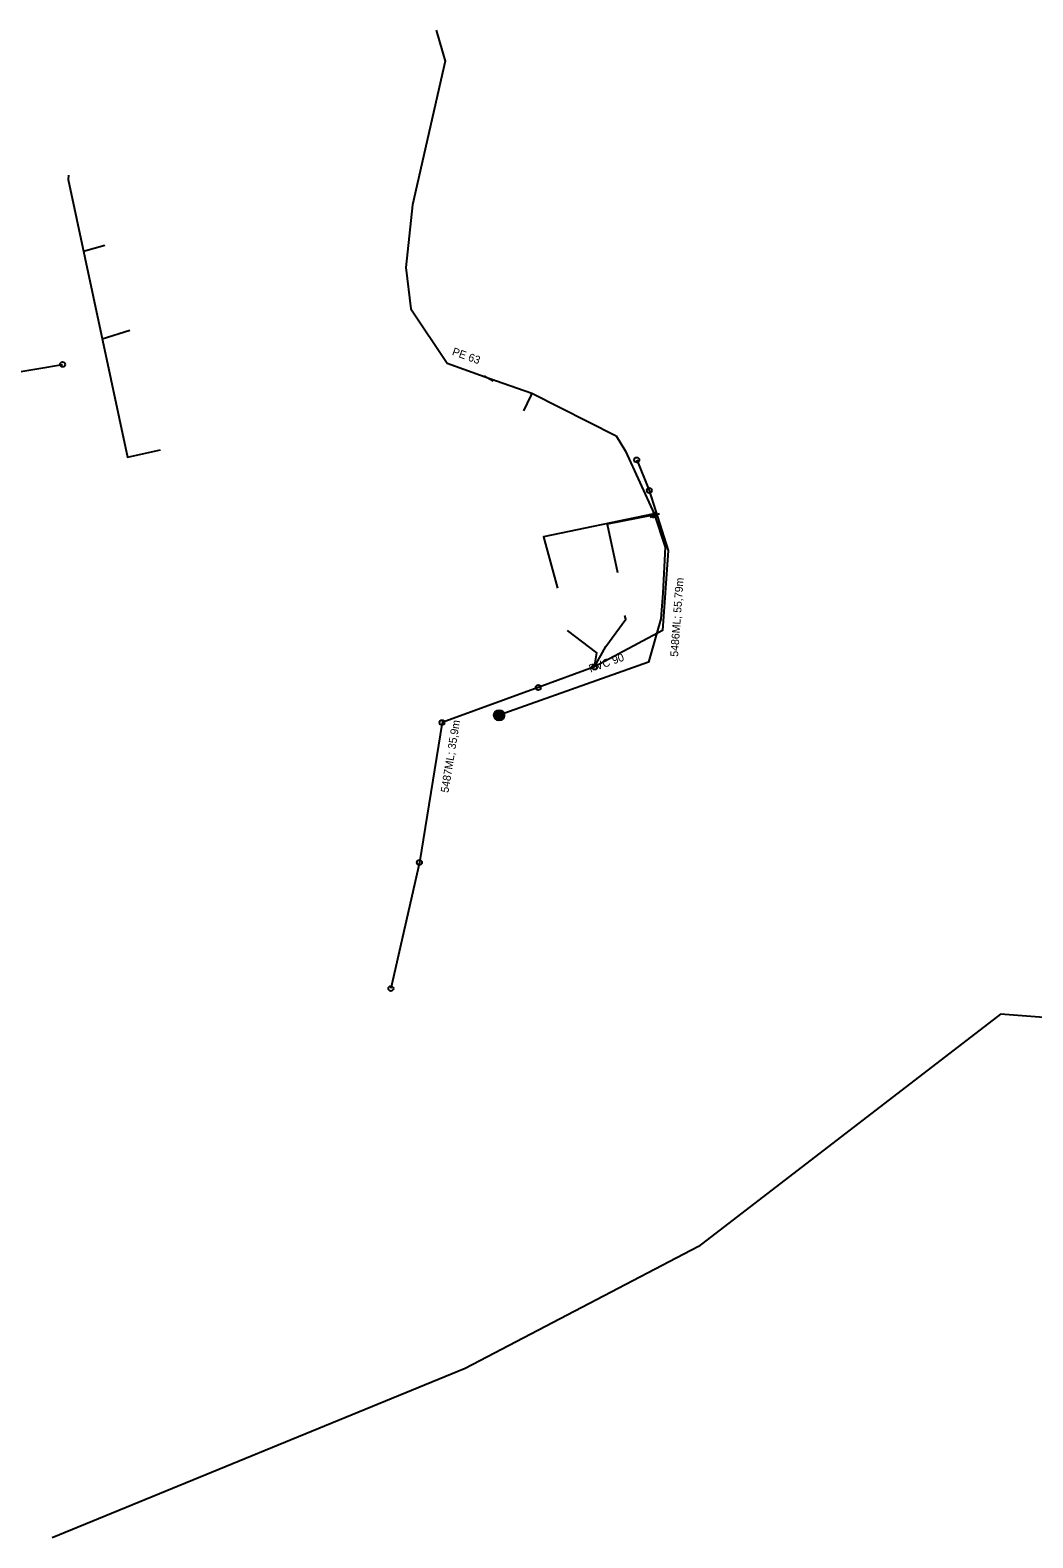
# Model space of a CAD drawing. Extents: x -867696 to -865033, y -1042522 to -1039817.
# Drawn here: x -865818.6 to -865564.5, y -1040306.4 to -1039924.3 of the extents above; entities that cross this region are included whole.
import ezdxf

# ---------------------------------------------------------------- set-up
doc = ezdxf.new("R2010")
doc.units = 0
for name, color, linetype in [('KN - destova', 7, 'Continuous'), ('KN - jednotna', 7, 'Continuous'), ('KN - popis usek delka', 7, 'Continuous'), ('KN - pripojka', 7, 'Continuous'), ('KN - sachta komora', 7, 'Continuous'), ('Level 1', 7, 'Continuous'), ('V - hydrant', 7, 'Continuous'), ('V - ostatni', 7, 'Continuous'), ('V - popis material', 7, 'Continuous'), ('V - pripojka', 7, 'Continuous'), ('V - rozvadeci', 7, 'Continuous')]:
    doc.layers.add(name, color=color, linetype=linetype)

# ---------------------------------------------------------------- blocks, each defined once
blk = doc.blocks.new('100.M')
at = {"layer": 'Level 1'}
blk.add_circle((0, 0), 1.27, dxfattribs=at)
blk = doc.blocks.new('111')
at = {"layer": 'Level 1'}
for p, q in [((0.42, 0.72), (-0.83, 0)), ((-0.83, 0), (0.42, -0.72)), ((0.42, -0.72), (0.42, 0.72))]:
    blk.add_line(p, q, dxfattribs=at)
blk = doc.blocks.new('160')
at = {"layer": 'Level 1'}
for p, q in [((-1.26, -0.04), (0.05, 1.27)), ((-1.26, -0.06), (0.06, 1.27)), ((-1.26, -0.07), (0.08, 1.27)), ((-1.26, -0.09), (0.09, 1.27)), ((-1.26, 0.11), (-0.12, 1.26)), ((-1.26, 0.1), (-0.1, 1.26)), ((-1.26, 0.08), (-0.09, 1.26)), ((-1.26, 0.07), (-0.07, 1.26)), ((-1.26, 0.06), (-0.06, 1.26)), ((-1.26, 0.04), (-0.04, 1.26)), ((-1.26, 0.03), (-0.03, 1.26)), ((-1.26, 0.01), (-0.01, 1.26)), ((-1.26, 0), (0, 1.26)), ((-1.26, -0.02), (0.02, 1.26)), ((-1.26, -0.03), (0.03, 1.26)), ((-1.26, -0.1), (0.1, 1.26)), ((-1.26, -0.11), (0.12, 1.26)), ((-1.26, -0.13), (0.13, 1.26)), ((-1.26, -0.14), (0.14, 1.26)), ((-1.26, 0.17), (-0.18, 1.25)), ((-1.26, 0.15), (-0.16, 1.25)), ((-1.26, 0.14), (-0.15, 1.25)), ((-1.26, 0.13), (-0.13, 1.25)), ((-1.26, -0.16), (0.15, 1.25)), ((-1.26, -0.17), (0.16, 1.25)), ((-1.25, 0.21), (-0.21, 1.25)), ((-1.25, 0.19), (-0.19, 1.25)), ((-1.25, -0.18), (0.17, 1.25)), ((-1.25, -0.19), (0.19, 1.25)), ((-1.25, -0.2), (0.2, 1.24)), ((-1.25, -0.21), (0.21, 1.24)), ((-1.24, 0.25), (-0.24, 1.25)), ((-1.24, 0.23), (-0.22, 1.25)), ((-1.24, -0.22), (0.22, 1.24)), ((-1.24, -0.24), (0.23, 1.24)), ((-1.24, -0.25), (0.25, 1.24)), ((-1.23, 0.27), (-0.26, 1.24)), ((-1.23, 0.29), (-0.28, 1.23)), ((-1.23, -0.26), (0.26, 1.23)), ((-1.23, -0.27), (0.27, 1.23)), ((-1.23, -0.28), (0.28, 1.23)), ((-1.23, -0.29), (0.29, 1.23)), ((-1.22, 0.3), (-0.3, 1.23)), ((-1.22, 0.32), (-0.32, 1.22)), ((-1.22, -0.3), (0.31, 1.22)), ((-1.22, -0.32), (0.32, 1.22)), ((-1.22, -0.33), (0.33, 1.22)), ((-1.21, -0.34), (0.34, 1.22)), ((-1.21, -0.35), (0.35, 1.22)), ((-1.21, 0.36), (-0.36, 1.21)), ((-1.21, 0.34), (-0.34, 1.21)), ((-1.21, -0.36), (0.36, 1.21)), ((-1.21, -0.37), (0.38, 1.21)), ((-1.2, -0.38), (0.39, 1.21)), ((-1.2, 0.38), (-0.38, 1.2)), ((-1.2, -0.39), (0.4, 1.2)), ((-1.2, -0.41), (0.41, 1.2)), ((-1.2, 0.4), (-0.4, 1.19)), ((-1.19, -0.42), (0.42, 1.2)), ((-1.19, 0.42), (-0.43, 1.19)), ((-1.19, -0.43), (0.43, 1.19)), ((-1.19, -0.44), (0.44, 1.19)), ((-1.19, 0.44), (-0.45, 1.18)), ((-1.19, -0.45), (0.45, 1.18)), ((-1.18, -0.46), (0.46, 1.18)), ((-1.18, 0.46), (-0.47, 1.17)), ((-1.18, -0.47), (0.47, 1.17)), ((-1.17, 0.48), (-0.49, 1.17)), ((-1.17, -0.48), (0.48, 1.17)), ((-1.17, -0.49), (0.49, 1.16)), ((-1.16, 0.51), (-0.51, 1.16)), ((-1.16, -0.5), (0.5, 1.16)), ((-1.16, -0.51), (0.5, 1.16)), ((-1.15, -0.52), (0.51, 1.15)), ((-1.15, -0.53), (0.52, 1.15)), ((-1.14, 0.54), (-0.53, 1.15)), ((-1.14, -0.54), (0.53, 1.14)), ((-1.14, -0.54), (0.54, 1.14)), ((-1.13, -0.55), (0.55, 1.13)), ((-1.13, -0.56), (0.56, 1.13)), ((-1.12, 0.58), (-0.56, 1.14)), ((-1.12, -0.57), (0.57, 1.12)), ((-1.12, -0.58), (0.58, 1.12)), ((-1.11, -0.59), (0.59, 1.11)), ((-1.11, -0.6), (0.6, 1.11)), ((-1.1, 0.61), (-0.6, 1.11)), ((-1.1, -0.61), (0.61, 1.11)), ((-1.1, -0.62), (0.62, 1.1)), ((-1.09, -0.63), (0.63, 1.1)), ((-1.09, 0.64), (-0.64, 1.09)), ((-1.09, -0.64), (0.64, 1.09)), ((-1.08, -0.65), (0.65, 1.09)), ((-1.08, -0.65), (0.66, 1.08)), ((-1.07, -0.66), (0.67, 1.08)), ((-1.07, -0.67), (0.68, 1.07)), ((-1.07, 0.67), (-0.68, 1.06)), ((-1.06, -0.68), (0.69, 1.07)), ((-1.06, -0.69), (0.69, 1.06)), ((-1.05, -0.7), (0.7, 1.05)), ((-1.05, -0.71), (0.71, 1.05)), ((-1.05, 0.7), (-0.71, 1.04)), ((-1.04, -0.72), (0.72, 1.04)), ((-1.04, -0.73), (0.72, 1.04)), ((-1.03, -0.74), (0.73, 1.03)), ((-1.03, -0.75), (0.74, 1.02)), ((-1.03, 0.73), (-0.75, 1.01)), ((-1.02, -0.75), (0.75, 1.02)), ((-1.01, -0.76), (0.76, 1.01)), ((-1.01, -0.77), (0.76, 1)), ((-1, -0.77), (0.77, 1)), ((-0.99, -0.78), (0.78, 0.99)), ((-0.99, -0.79), (0.79, 0.98)), ((-0.98, -0.8), (0.79, 0.98)), ((-0.97, -0.8), (0.8, 0.97)), ((-0.97, -0.81), (0.81, 0.97)), ((-0.96, -0.82), (0.82, 0.96)), ((-0.95, -0.83), (0.83, 0.95)), ((-0.95, -0.83), (0.83, 0.95)), ((-0.94, -0.84), (0.84, 0.94)), ((-0.93, -0.85), (0.85, 0.93)), ((-0.93, -0.86), (0.86, 0.93)), ((-0.92, -0.86), (0.86, 0.92)), ((-0.91, 0.87), (-0.79, 0.99)), ((-0.91, -0.87), (0.87, 0.91)), ((-0.91, -0.88), (0.88, 0.91)), ((-0.9, -0.88), (0.89, 0.9)), ((-0.89, -0.89), (0.89, 0.89)), ((-0.88, -0.9), (0.9, 0.89)), ((-0.88, -0.91), (0.91, 0.88)), ((-0.87, -0.91), (0.92, 0.88)), ((-0.86, -0.92), (0.93, 0.87)), ((-0.86, -0.93), (0.93, 0.86)), ((-0.85, -0.94), (0.94, 0.85)), ((-0.84, -0.94), (0.94, 0.84)), ((-0.84, -0.95), (0.95, 0.84)), ((-0.83, -0.96), (0.96, 0.83)), ((-0.82, -0.96), (0.96, 0.82)), ((-0.82, -0.97), (0.97, 0.81)), ((-0.81, -0.98), (0.97, 0.8)), ((-0.8, -0.98), (0.98, 0.8)), ((-0.79, -0.99), (0.99, 0.79)), ((-0.78, -1), (0.99, 0.78)), ((-0.77, -1), (1, 0.77)), ((-0.77, -1.01), (1, 0.76)), ((-0.76, -1.01), (1.01, 0.75)), ((-0.75, -1.02), (1.02, 0.75)), ((-0.74, -1.02), (1.02, 0.74)), ((-0.73, -1.03), (1.03, 0.73)), ((-0.72, -1.03), (1.03, 0.72)), ((-0.71, -1.04), (1.04, 0.71)), ((-0.71, -1.04), (1.04, 0.71)), ((-0.7, -1.05), (1.05, 0.7)), ((-0.69, -1.06), (1.06, 0.69)), ((-0.68, -1.06), (1.06, 0.68)), ((-0.67, -1.07), (1.07, 0.67)), ((-0.66, -1.07), (1.07, 0.66)), ((-0.65, -1.08), (1.08, 0.66)), ((-0.64, -1.08), (1.09, 0.65)), ((-0.64, -1.09), (1.09, 0.64)), ((-0.63, -1.09), (1.1, 0.63)), ((-0.62, -1.1), (1.1, 0.62)), ((-0.61, -1.11), (1.11, 0.62)), ((-0.6, -1.11), (1.12, 0.61)), ((-0.59, -1.12), (1.12, 0.6)), ((-0.58, -1.12), (1.12, 0.59)), ((-0.58, -1.13), (1.13, 0.58)), ((-0.57, -1.13), (1.13, 0.57)), ((-0.56, -1.14), (1.14, 0.56)), ((-0.55, -1.14), (1.14, 0.55)), ((-0.54, -1.15), (1.14, 0.54)), ((-0.53, -1.15), (1.15, 0.52)), ((-0.52, -1.16), (1.15, 0.51)), ((-0.51, -1.16), (1.16, 0.5)), ((-0.5, -1.16), (1.16, 0.49)), ((-0.49, -1.17), (1.16, 0.48)), ((-0.48, -1.17), (1.17, 0.47)), ((-0.47, -1.17), (1.17, 0.46)), ((-0.46, -1.18), (1.18, 0.45)), ((-0.44, -1.18), (1.18, 0.44)), ((-0.43, -1.18), (1.18, 0.43)), ((-0.42, -1.19), (1.19, 0.42)), ((-0.41, -1.19), (1.19, 0.41)), ((-0.4, -1.19), (1.2, 0.4)), ((-0.39, -1.2), (1.2, 0.39)), ((-0.38, -1.2), (1.2, 0.38)), ((-0.37, -1.2), (1.21, 0.37)), ((-0.36, -1.21), (1.21, 0.36)), ((-0.35, -1.21), (1.22, 0.35)), ((-0.34, -1.22), (1.22, 0.34)), ((-0.33, -1.22), (1.22, 0.33)), ((-0.32, -1.22), (1.23, 0.32)), ((-0.31, -1.23), (1.23, 0.31)), ((-0.3, -1.23), (1.23, 0.3)), ((-0.28, -1.23), (1.23, 0.29)), ((-0.27, -1.24), (1.24, 0.27)), ((-0.26, -1.24), (1.24, 0.26)), ((-0.25, -1.24), (1.24, 0.25)), ((-0.24, -1.25), (1.24, 0.24)), ((-0.23, -1.25), (1.24, 0.22)), ((-0.22, -1.25), (1.24, 0.21)), ((-0.2, -1.25), (1.24, 0.2)), ((-0.19, -1.25), (1.25, 0.19)), ((-0.18, -1.25), (1.25, 0.17)), ((-0.16, -1.25), (1.25, 0.16)), ((-0.15, -1.25), (1.25, 0.15)), ((-0.14, -1.25), (1.25, 0.14)), ((-0.12, -1.25), (1.25, 0.12)), ((-0.11, -1.26), (1.26, 0.11)), ((-0.1, -1.26), (1.26, 0.1)), ((-0.08, -1.26), (1.26, 0.09)), ((-0.07, -1.26), (1.26, 0.07)), ((-0.06, -1.26), (1.26, 0.06)), ((-0.04, -1.26), (1.26, 0.05)), ((-0.03, -1.26), (1.27, 0.04)), ((-0.02, -1.26), (1.27, 0.02)), ((0, -1.26), (1.27, 0.01)), ((0.01, -1.26), (1.27, 0)), ((0.02, -1.26), (1.27, -0.02)), ((0.04, -1.27), (1.27, -0.04)), ((0.05, -1.27), (1.26, -0.05)), ((0.06, -1.27), (1.26, -0.07)), ((0.08, -1.27), (1.26, -0.08)), ((0.09, -1.26), (1.26, -0.1)), ((0.11, -1.26), (1.26, -0.12)), ((0.13, -1.26), (1.25, -0.13)), ((0.15, -1.25), (1.25, -0.15)), ((0.16, -1.25), (1.25, -0.17)), ((0.18, -1.25), (1.25, -0.18)), ((0.2, -1.24), (1.24, -0.2)), ((0.22, -1.24), (1.24, -0.21)), ((0.23, -1.24), (1.24, -0.23)), ((0.25, -1.24), (1.24, -0.25)), ((0.27, -1.23), (1.24, -0.26)), ((0.28, -1.23), (1.23, -0.28)), ((0.3, -1.23), (1.23, -0.3)), ((0.32, -1.22), (1.23, -0.31)), ((0.34, -1.22), (1.22, -0.33)), ((0.35, -1.22), (1.22, -0.35)), ((0.37, -1.21), (1.21, -0.38)), ((0.39, -1.21), (1.2, -0.4)), ((0.42, -1.2), (1.19, -0.43)), ((0.44, -1.18), (1.18, -0.45)), ((0.47, -1.17), (1.17, -0.47)), ((0.5, -1.16), (1.16, -0.5)), ((0.52, -1.15), (1.15, -0.52)), ((0.55, -1.13), (1.14, -0.54)), ((0.58, -1.12), (1.13, -0.57)), ((0.6, -1.11), (1.12, -0.59)), ((0.63, -1.1), (1.11, -0.61)), ((0.65, -1.09), (1.08, -0.66)), ((0.69, -1.06), (1.04, -0.72)), ((0.77, -1), (1, -0.77)), ((0.85, -0.93), (0.96, -0.82))]:
    blk.add_line(p, q, dxfattribs=at)
blk.add_circle((0, 0), 1.27, dxfattribs=at)
blk = doc.blocks.new('150')
at = {"layer": 'Level 1'}
blk.add_line((0, 1.27), (0, -1.27), dxfattribs=at)

msp = doc.modelspace()

# ---------------------------------------------------------------- linework, layer by layer
at = {"layer": 'KN - destova'}
for points in [[(-865664.88, -1040033.27), (-865661.69, -1040041.01)], [(-865661.69, -1040041.01), (-865656.911, -1040056.228), (-865658.349, -1040076.478), (-865675.55, -1040085.74)], [(-865675.55, -1040085.74), (-865689.828, -1040090.946)], [(-865689.828, -1040090.946), (-865714.225, -1040099.841)], [(-865714.225, -1040099.841), (-865719.955, -1040135.278)], [(-865719.955, -1040135.278), (-865727.195, -1040167.235)]]:
    msp.add_lwpolyline(points, dxfattribs=at)
at = {"layer": 'KN - jednotna'}
msp.add_lwpolyline([(-865845.071, -1040014.883), (-865810.373, -1040009.065)], dxfattribs=at)
at = {"layer": 'KN - pripojka'}
for points in [[(-865675.55, -1040085.74), (-865672.7, -1040080.51), (-865667.68, -1040073.66), (-865667.93, -1040072.69)], [(-865675.55, -1040085.74), (-865675.01, -1040082.11), (-865682.43, -1040076.46)]]:
    msp.add_lwpolyline(points, dxfattribs=at)
at = {"layer": 'V - pripojka'}
for points in [[(-865808.892, -1039961.094), (-865808.942, -1039962.184), (-865793.957, -1040032.569), (-865785.575, -1040030.74)], [(-865805.08, -1039980.323), (-865799.635, -1039978.806)], [(-865800.349, -1040002.545), (-865793.318, -1040000.414)], [(-865702.352, -1040012.504), (-865702.445, -1040012.666)], [(-865691.441, -1040016.376), (-865691.707, -1040016.923), (-865693.546, -1040020.815)], [(-865660.47, -1040046.894), (-865660.85, -1040047.03), (-865688.54, -1040052.72), (-865685, -1040065.75)], [(-865660.342, -1040047.181), (-865660.7, -1040047.27), (-865672.336, -1040049.542), (-865669.74, -1040061.8)], [(-865660.342, -1040047.181), (-865660.21, -1040047.53)], [(-865699.752, -1040097.979), (-865700.643, -1040098.228)], [(-865510, -1040153.97), (-865544.067, -1040175.886), (-865572.682, -1040173.74), (-865649.227, -1040232.639), (-865708.365, -1040263.52), (-865813.049, -1040306.443)]]:
    msp.add_lwpolyline(points, dxfattribs=at)
at = {"layer": 'V - rozvadeci'}
for points in [[(-865715.713, -1039924.342), (-865713.407, -1039932.236), (-865721.736, -1039968.599), (-865723.384, -1039984.525), (-865722.103, -1039994.959), (-865712.938, -1040008.748), (-865702.352, -1040012.504), (-865691.441, -1040016.376), (-865670.116, -1040027.176), (-865667.736, -1040031.02), (-865660.47, -1040046.894), (-865660.342, -1040047.181)], [(-865660.342, -1040047.181), (-865657.704, -1040055.402), (-865658.233, -1040067.038), (-865658.762, -1040073.517), (-865661.936, -1040084.492), (-865699.752, -1040097.979)]]:
    msp.add_lwpolyline(points, dxfattribs=at)

# ---------------------------------------------------------------- block references
at = {"layer": 'KN - sachta komora'}
for p, xscale, yscale, rotation in [((-865810.373, -1040009.065), 0.5036654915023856, 0.5036654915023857, 12.13890866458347), ((-865664.88, -1040033.27), 0.5000000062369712, 0.500000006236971, 112.99999954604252), ((-865661.69, -1040041.01), 0.4999999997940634, 0.4999999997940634, -69.99999934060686), ((-865675.55, -1040085.74), 0.5084781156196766, 0.5084781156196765, 26.97601645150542), ((-865689.828, -1040090.946), 0.5137536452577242, 0.513753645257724, 24.689105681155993), ((-865714.225, -1040099.841), 0.500000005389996, 0.5000000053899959, 51.00000108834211), ((-865719.955, -1040135.278), 0.49999998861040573, 0.4999999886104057, 79.99999971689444), ((-865727.195, -1040167.235), 0.5000000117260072, 0.5000000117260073, -101.99999938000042)]:
    msp.add_blockref('100.M', p, dxfattribs=dict(at, xscale=xscale, yscale=yscale, rotation=rotation))
at = {"layer": 'V - hydrant'}
for p, xscale, yscale, rotation in [((-865702.399, -1040012.585), 1.0000000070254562, 1.0000000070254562, 61.000001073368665), ((-865660.276, -1040047.355), 0.9999999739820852, 0.9999999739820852, -68.99999941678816)]:
    msp.add_blockref('150', p, dxfattribs=dict(at, xscale=xscale, yscale=yscale, rotation=rotation))
at = {"layer": 'V - ostatni'}
for name, p, xscale, yscale, rotation in [('111', (-865660.342, -1040047.181), 0.9999999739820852, 0.9999999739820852, -68.99999941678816), ('160', (-865699.752, -1040097.979), 1.0296949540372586, 1.0296949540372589, -155.86620948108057)]:
    msp.add_blockref(name, p, dxfattribs=dict(at, xscale=xscale, yscale=yscale, rotation=rotation))

# ---------------------------------------------------------------- texts
at = {"layer": 'KN - popis usek delka'}
for s, rotation, p in [('5486ML; 55,79m', 85.94, (-865654.414, -1040083.192)), ('5487ML; 35,9m', 80.82, (-865712.609, -1040117.696))]:
    msp.add_text(s, height=1.99999, rotation=rotation, dxfattribs=at).set_placement(p)
at = {"layer": 'V - popis material'}
for s, rotation, p in [('PE 63', 340.46, (-865711.834, -1040006.593)), ('PVC 90', 19.63, (-865676.581, -1040087.166))]:
    msp.add_text(s, height=2, rotation=rotation, dxfattribs=at).set_placement(p)

doc.saveas('drawing.dxf')
